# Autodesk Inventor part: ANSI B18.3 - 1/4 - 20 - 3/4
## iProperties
Comments: To add or edit properties for Autodesk Inventor files, use iProperties.
Created: 2004-08
Part Number: ANSI B18.3 - 1/4 - 20 - 3/4
Vendor: Autodesk Inc.
Document SubType Name: Modeling
Designer: John Blackburn
Material: Default
Description: Hexagon Socket Head Cap Screw
Standard: ANSI B18.3
Alert: To add or edit properties for Autodesk Inventor files, use iProperties.
Control State: 0
Master: False
Checked Out: False
Shininess: 64.0
Length Units: 11272
Angle Units: 11279
Time Units: 11290
Mass Units: 11286
Length Display Precision: 3
Angle Display Precision: 2
Compacted: True
EGR: 3
Classification: un/spsc 31161501
Density: 0.0
Volumn: 0.0
Area: 0.0
PropertySet Name: Model Information
Author: John Blackburn
Revision Number: 8
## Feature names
1. Body [Revolution]
2. Slot [Extrusion]
3. Fillet1
4. Chamfer1
